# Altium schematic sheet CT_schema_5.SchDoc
size 383 x 296 mm
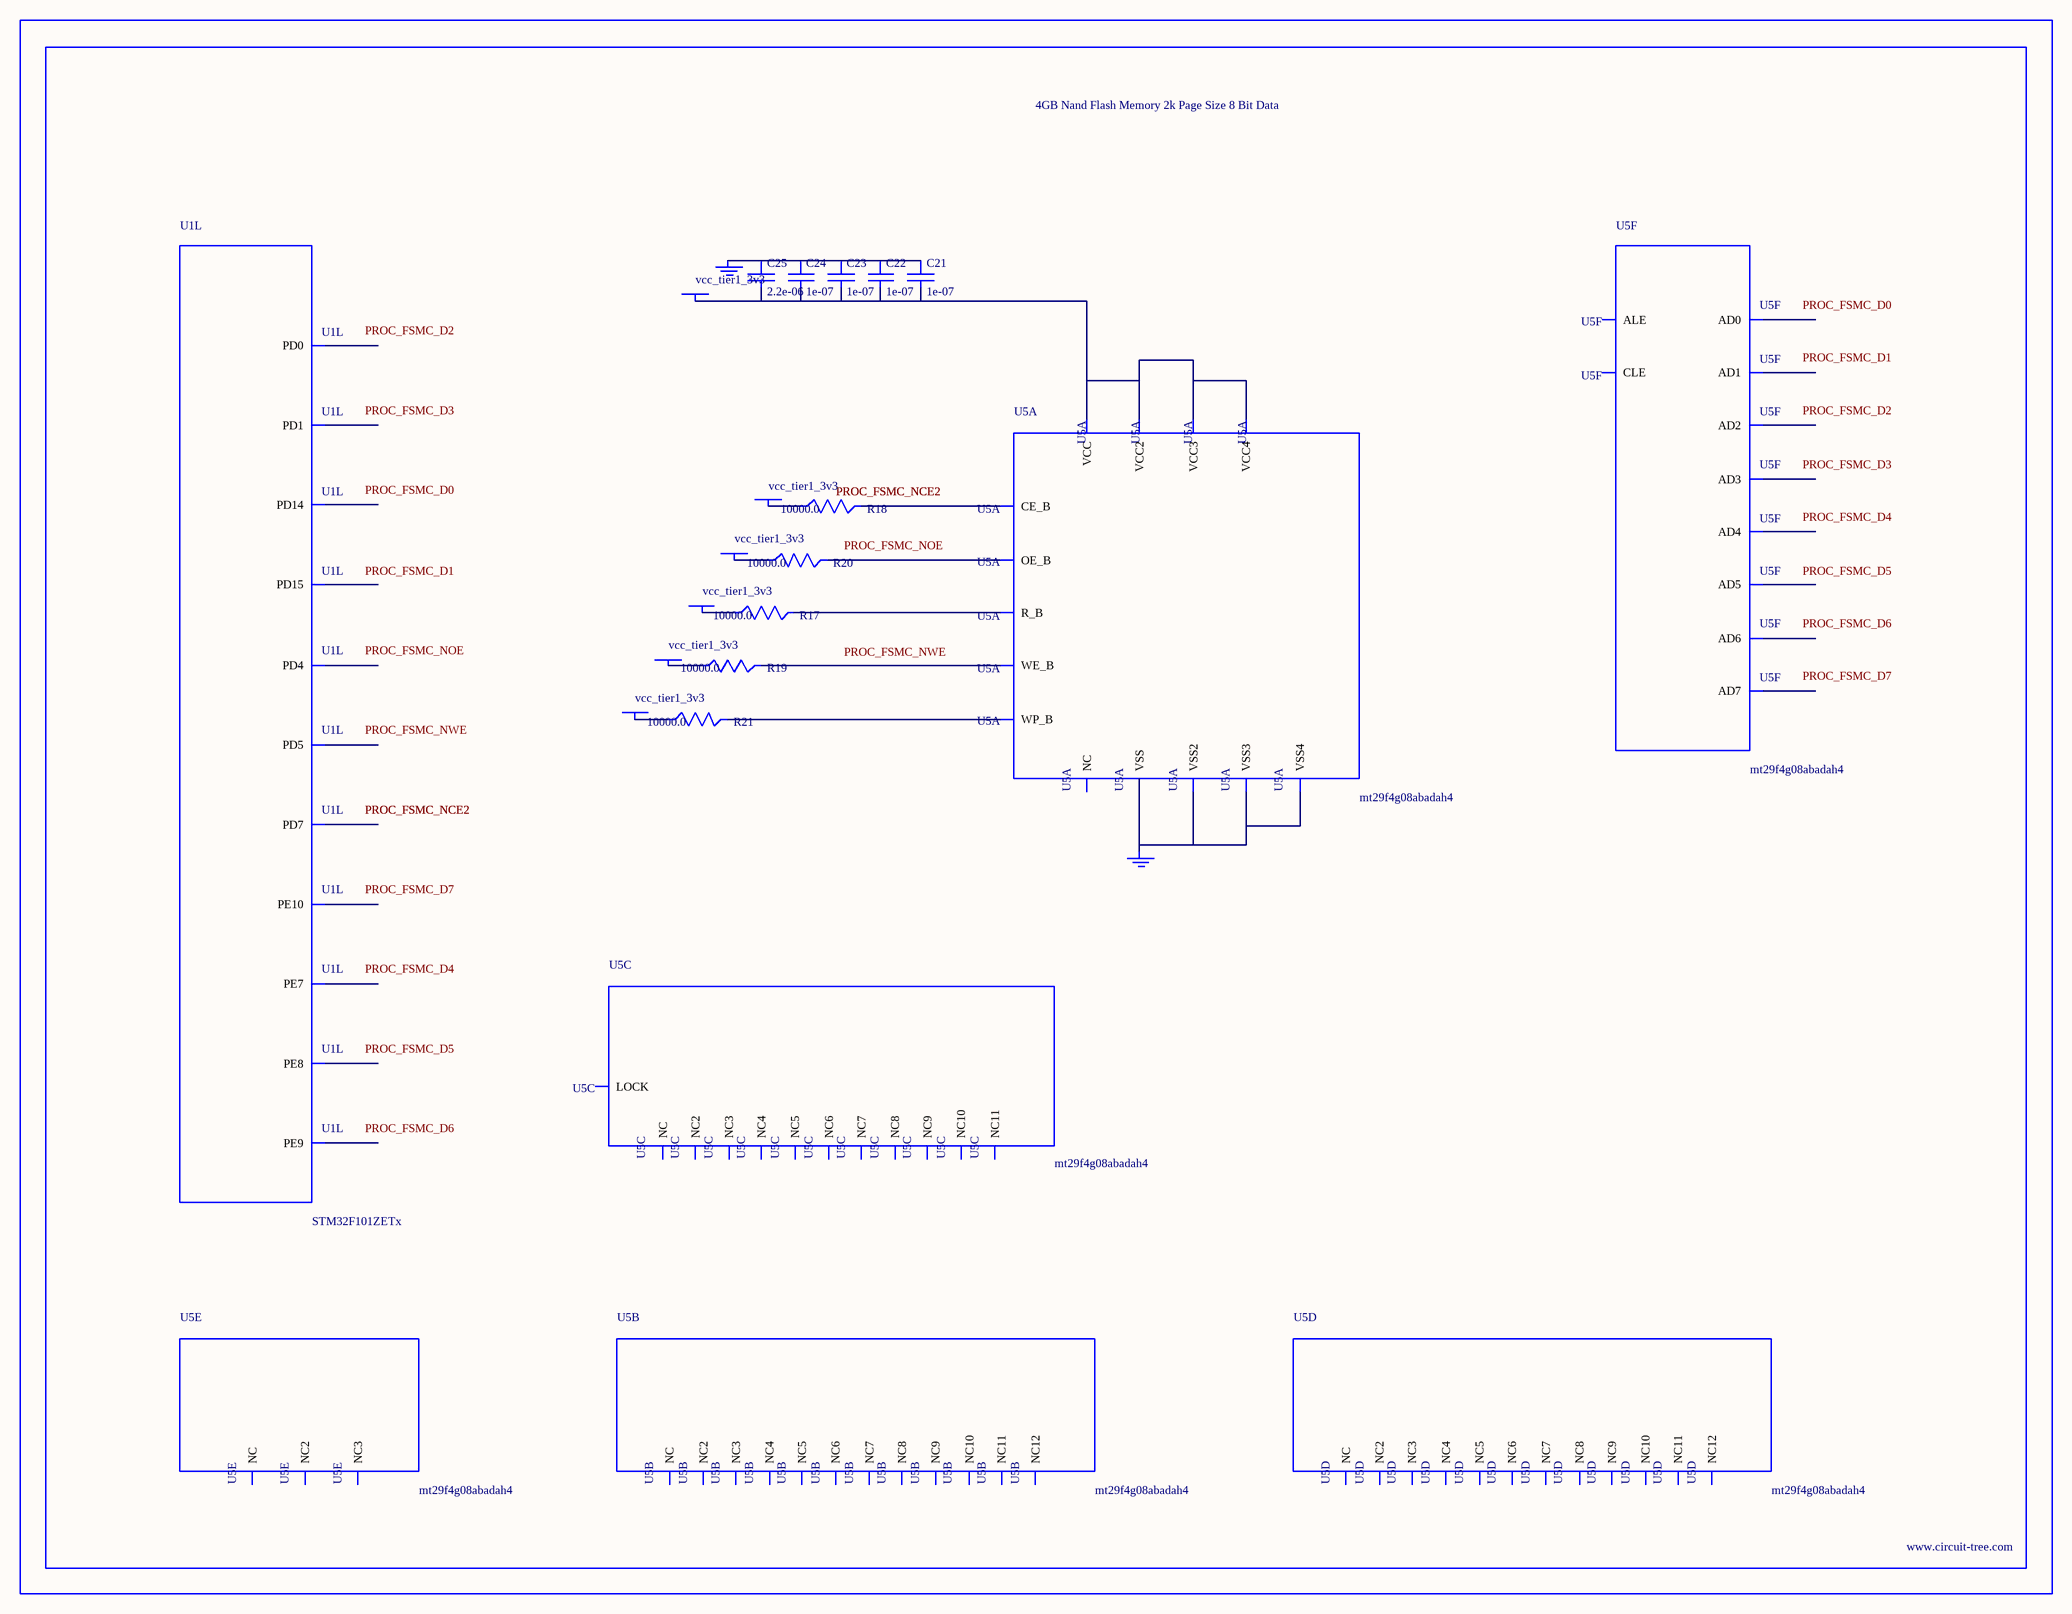
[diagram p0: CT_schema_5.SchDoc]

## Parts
BORDER4  (no value)
C21  1e-07  [C0402]
C22  1e-07  [C0402]
C23  1e-07  [C0402]
C24  1e-07  [C0402]
C25  2.2e-06  [C0603]
GND_INSTANCE_4_0  (no value)
GND_INSTANCE_4_1  (no value)
POWER_INSTANCE_4_0  vcc_tier1_3v3
POWER_INSTANCE_4_1  vcc_tier1_3v3
POWER_INSTANCE_4_2  vcc_tier1_3v3
POWER_INSTANCE_4_3  vcc_tier1_3v3
POWER_INSTANCE_4_4  vcc_tier1_3v3
POWER_INSTANCE_4_5  vcc_tier1_3v3
R17  10000.0  [R0603]
R18  10000.0  [R0603]
R19  10000.0  [R0603]
R20  10000.0  [R0603]
R21  10000.0  [R0603]
U1  STM32F101ZETx  [LQFP144]  (part L of 12)
U5  mt29f4g08abadah4  [VFBGA-63]  (parts A,B,C,D,E,F of 6)

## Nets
NetC21_1: C21.1 C22.1 C23.1 C24.1 C25.1 GND_INSTANCE_4_0.0(GND)
NetC21_2: C21.2 C22.2 C23.2 C24.2 C25.2 POWER_INSTANCE_4_0.0(PWR) U5.D3(VCC) U5.G4(VCC2) U5.H8(VCC3) U5.J6(VCC4)
NetGND_INSTANCE_4_1_0: GND_INSTANCE_4_1.0(GND) U5.C5(VSS) U5.F7(VSS2) U5.K3(VSS3) U5.K8(VSS4)
NetPOWER_INSTANCE_4_1_0: POWER_INSTANCE_4_1.0(PWR) R17.1
NetPOWER_INSTANCE_4_2_0: POWER_INSTANCE_4_2.0(PWR) R18.1
NetPOWER_INSTANCE_4_3_0: POWER_INSTANCE_4_3.0(PWR) R19.1
NetPOWER_INSTANCE_4_4_0: POWER_INSTANCE_4_4.0(PWR) R20.1
NetPOWER_INSTANCE_4_5_0: POWER_INSTANCE_4_5.0(PWR) R21.1
NetR17_2: R17.2 U5.C8(R_B)
NetR18_2: R18.2 U5.C6(CE_B)
NetR19_2: R19.2 U5.C7(WE_B)
NetR20_2: R20.2 U5.D4(OE_B)
NetR21_2: R21.2 U5.C3(WP_B)

Not connected (* = marked no-connect by the designer): U1 58(PE7) 59(PE8) 60(PE9) 63(PE10) 85(PD14) 86(PD15) 114(PD0) 115(PD1) 118(PD4) 119(PD5) 123(PD7); U5 A1(NC) A2(NC3) A9(NC4) A10(NC2) B1(NC5) B9(NC7) B10(NC6) C4(ALE) D5(CLE) D6(NC8) D7(NC9) D8(NC10) E3(NC11) E4(NC12) E5(NC) E6(NC2) E7(NC3) E8(NC4) F3(NC5) F4(NC6) F5(NC7) F6(NC8) F8(NC9) G3(NC) G5(LOCK) G6(NC10) G7(NC11) G8(NC) H3(NC2) H4(AD0) H5(NC3) H6(NC4) H7(NC5) J3(NC6) J4(AD1) J5(NC7) J7(AD5) J8(AD7) K4(AD2) K5(AD3) K6(AD4) K7(AD6) L1(NC8) L2(NC10) L9(NC11) L10(NC9) M1(NC12) M2(NC2) M9(NC3) M10(NC)

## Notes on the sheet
- Labels drawn without touching a wire or pin: PROC_FSMC_D0, PROC_FSMC_D1, PROC_FSMC_D2, PROC_FSMC_D3, PROC_FSMC_D4, PROC_FSMC_D5, PROC_FSMC_D6, PROC_FSMC_D7, PROC_FSMC_NOE, PROC_FSMC_NWE

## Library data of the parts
BORDER4 = BORDER_PAGE4
C21-C24 = C0402C104K3RACTU
C25 = C0603C225K8RACTU
GND_INSTANCE_4_0 GND_INSTANCE_4_1 = GND
POWER_INSTANCE_4_0-POWER_INSTANCE_4_5 = PWR
R17-R21 = RC0603JR-0710KL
